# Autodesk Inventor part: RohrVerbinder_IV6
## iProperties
Shininess: 64.0
Length Units: 11269
Angle Units: 11279
Time Units: 11290
Mass Units: 11283
Length Display Precision: 5
Angle Display Precision: 5
Compacted: True
Part Number: RohrVerbinder_IV6
Document SubType Name: Modeling
Created: 2005-04
Material: Aluminium - 6061
Designer: mp
Density: 0.0
Volumn: 0.0
Area: 0.0
PropertySet Name: Model Information
Control State: 0
Master: False
Checked Out: False
Author: mp
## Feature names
1. Extrusion1
2. Extrusion2
3. Bohrung1 [Hole]
4. Spiegeln1 [Mirror]
5. Rundung1 [Fillet]
6. Fase1 [Chamfer]
